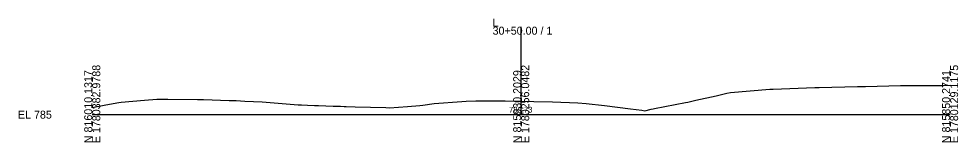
# Model space of a CAD drawing. Extents: x -26 to 7903, y -10 to 9573.
# Drawn here: x -25.7 to 302.8, y 1490.3 to 1533.7 of the extents above; entities that cross this region are included whole.
import ezdxf

# ---------------------------------------------------------------- set-up
doc = ezdxf.new("R2010")
doc.units = 0
for name, color, linetype in [('Exist Cross Section Cell', 7, 'Continuous'), ('Exist XS Center Line Elevation Label', 7, 'Continuous'), ('Exist XS Ground Line', 7, 'Continuous')]:
    doc.layers.add(name, color=color, linetype=linetype)

msp = doc.modelspace()

# ---------------------------------------------------------------- linework, layer by layer
at = {"layer": 'Exist Cross Section Cell'}
for p, q in [((150, 1500), (150, 1530.86)), ((0, 1500), (150, 1500)), ((150, 1500), (300, 1500))]:
    msp.add_line(p, q, dxfattribs=at)
at = {"layer": 'Exist XS Ground Line'}
for p, q in [((223.26, 1507.83), (236.96, 1508.89)), ((236.96, 1508.89), (237.63, 1508.93)), ((237.63, 1508.93), (238.18, 1508.95)), ((238.18, 1508.95), (252.65, 1509.55)), ((252.65, 1509.55), (254.22, 1509.54)), ((254.22, 1509.54), (267.67, 1509.91)), ((267.67, 1509.91), (270.4, 1509.92)), ((270.4, 1509.92), (282.7, 1510.2)), ((282.7, 1510.2), (286.2, 1510.27)), ((286.2, 1510.27), (297.64, 1510.22)), ((297.64, 1510.22), (300, 1510.29)), ((10.07, 1504.35), (18.25, 1505.03)), ((18.25, 1505.03), (22.61, 1505.39)), ((22.61, 1505.39), (25.57, 1505.42)), ((25.57, 1505.42), (26.46, 1505.42)), ((26.46, 1505.42), (36.76, 1505.29)), ((36.76, 1505.29), (38.96, 1505.26)), ((38.96, 1505.26), (47.92, 1505.01)), ((47.92, 1505.01), (49.75, 1504.95)), ((49.75, 1504.95), (50.35, 1504.93)), ((50.35, 1504.93), (53.35, 1504.79)), ((53.35, 1504.79), (59.44, 1504.51)), ((129.23, 1504.58), (130.71, 1504.7)), ((130.71, 1504.7), (134.19, 1504.82)), ((134.19, 1504.82), (137.36, 1504.89)), ((137.36, 1504.89), (144.39, 1504.81)), ((144.39, 1504.81), (149.04, 1504.75)), ((149.04, 1504.75), (150, 1504.73)), ((150, 1504.73), (154.46, 1504.63)), ((208.23, 1504.43), (211.05, 1505.04)), ((211.05, 1505.04), (218.14, 1506.59)), ((218.14, 1506.59), (221.94, 1507.49)), ((221.94, 1507.49), (223.26, 1507.83)), ((0, 1502.5), (4.74, 1503.43)), ((4.74, 1503.43), (9.33, 1504.29)), ((9.33, 1504.29), (10.07, 1504.35)), ((59.44, 1504.51), (72, 1503.5)), ((72, 1503.5), (73.12, 1503.46)), ((73.12, 1503.46), (75.24, 1503.35)), ((75.24, 1503.35), (77.67, 1503.25)), ((77.67, 1503.25), (78.44, 1503.19)), ((78.44, 1503.19), (79.08, 1503.17)), ((79.08, 1503.17), (84.28, 1503)), ((84.28, 1503), (86.85, 1502.92)), ((86.85, 1502.92), (88.04, 1502.88)), ((88.04, 1502.88), (88.84, 1502.85)), ((88.84, 1502.85), (91.94, 1502.78)), ((91.94, 1502.78), (102.68, 1502.47)), ((102.68, 1502.47), (103.91, 1502.45)), ((103.91, 1502.45), (110.26, 1502.9)), ((110.26, 1502.9), (114.56, 1503.21)), ((114.56, 1503.21), (115.62, 1503.34)), ((115.62, 1503.34), (119.62, 1503.87)), ((119.62, 1503.87), (129.23, 1504.58)), ((154.46, 1504.63), (160.93, 1504.48)), ((160.93, 1504.48), (169.83, 1504.12)), ((169.83, 1504.12), (172.78, 1503.87)), ((172.78, 1503.87), (179.16, 1503.22)), ((179.16, 1503.22), (188.26, 1502.02)), ((188.26, 1502.02), (192.14, 1501.52)), ((192.14, 1501.52), (193.22, 1501.38)), ((193.22, 1501.38), (195.46, 1501.9)), ((195.46, 1501.9), (196.11, 1502.06)), ((196.11, 1502.06), (196.67, 1502.17)), ((196.67, 1502.17), (207.5, 1504.25)), ((207.5, 1504.25), (208.23, 1504.43))]:
    msp.add_line(p, q, dxfattribs=at)

# ---------------------------------------------------------------- texts
at = {"layer": 'Exist Cross Section Cell'}
for s, p in [('30+50.00 / 1', (140, 1528.06)), ('L', (140, 1530.86)), ('EL 785', (-26, 1498.6))]:
    msp.add_text(s, height=2.8, dxfattribs=at).set_placement(p)
for s, p in [('N 816010.1317', (0, 1490)), ('E 1780382.9788', (2.8, 1490)), ('N 815930.2029', (150, 1490)), ('E 1780256.0482', (152.8, 1490)), ('N 815850.2741', (300, 1490)), ('E 1780129.1175', (302.8, 1490))]:
    msp.add_text(s, height=2.8, rotation=90, dxfattribs=at).set_placement(p)
at = {"layer": 'Exist XS Center Line Elevation Label'}
msp.add_text('789.73', height=2, dxfattribs=at).set_placement((145.75, 1500.73))

doc.saveas('drawing.dxf')
